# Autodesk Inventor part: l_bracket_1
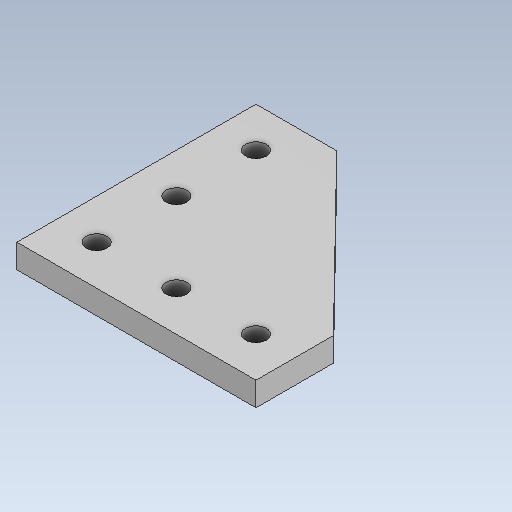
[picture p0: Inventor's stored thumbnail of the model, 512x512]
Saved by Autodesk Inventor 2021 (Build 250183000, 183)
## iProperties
Created: 2026-10
Part Number: l_bracket_1
Material: Steel
Document SubType Name: Modeling
Designer: hp
Density: 7.85 g/cm^3
Appearance: Default
Author: hp
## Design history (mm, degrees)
feature "Body1"
body "Solid1"
